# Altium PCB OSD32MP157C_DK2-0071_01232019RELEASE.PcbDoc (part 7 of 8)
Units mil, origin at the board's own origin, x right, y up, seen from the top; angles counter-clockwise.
Board outline 3976.38 x 2795.28 mil, 6 copper layers (Top Layer, Signal Layer 1, Signal Layer 2, Signal Layer 3, Signal Layer 4, Bottom Layer), stack 61.268 mil thick; 404 components, 418 nets, 1720 pads, 1233 vias.
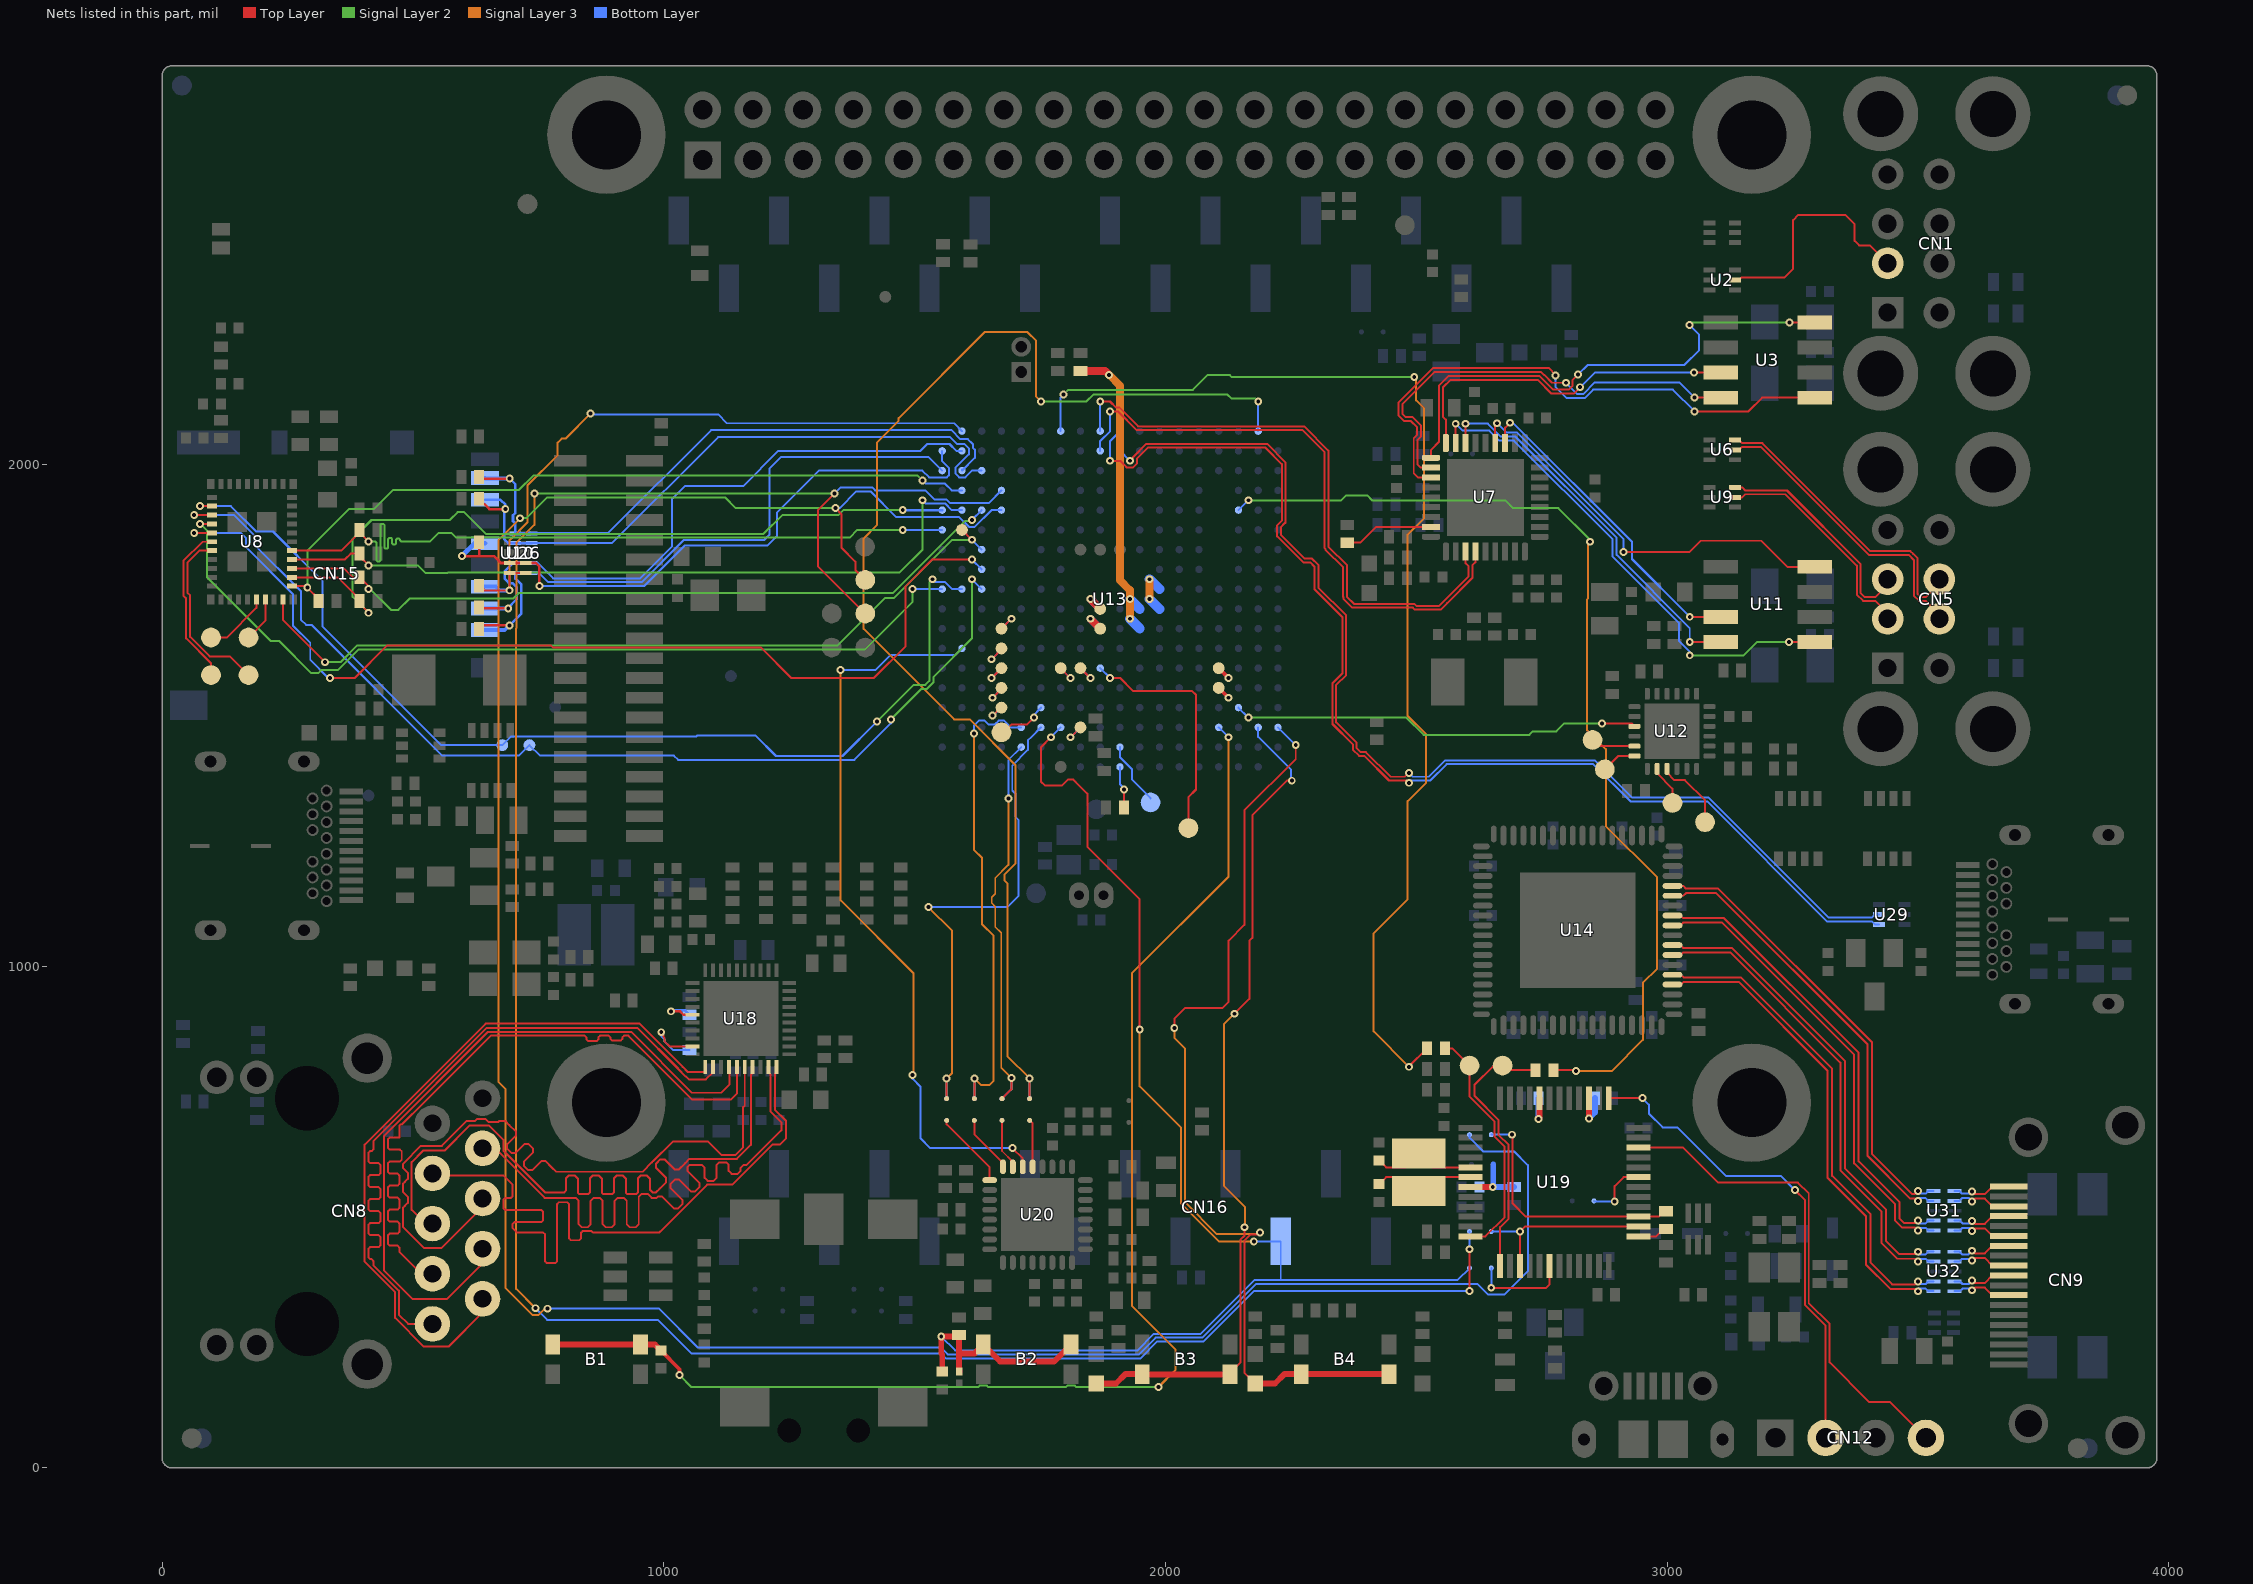
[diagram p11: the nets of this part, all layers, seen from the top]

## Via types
v1: diameter 15.75, hole 7.87, Top Layer to Bottom Layer, tented both sides, 803 vias
v2: diameter 23.62, hole 11.81, Top Layer to Bottom Layer, tented both sides, 417 vias
v3: diameter 15.75, hole 7.87, Top Layer to Bottom Layer, 13 vias

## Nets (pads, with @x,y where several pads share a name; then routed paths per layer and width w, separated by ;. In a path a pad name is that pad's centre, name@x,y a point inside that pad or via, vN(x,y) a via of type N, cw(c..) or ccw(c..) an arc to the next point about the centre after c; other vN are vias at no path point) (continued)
NetR153_2: R153.2 U18.35 | length 86.1
  Top Layer w5.12: v1(1014.76,910.43) 1032.48,910.43 1039.37,903.54 U18.35@1057.09,903.54
  Bottom Layer w5.12: v1(1014.76,910.43) 1020.67,910.43 1022.64,912.4 1042.32,912.4 R153.2@1051.18,903.54
NetR155_1: R155.1 U18.39 | length 158.6
  Top Layer w3.94: v1(995.02,868.7) 995.08,868.65 994.54,868.11 999.02,863.64 999.02,859.56 1001.03,857.54 1001.03,850.98 1011.41,840.6 1025.99,840.6 1026.04,840.55 U18.39@1057.09,840.55
  Bottom Layer w3.94: v1(995.02,868.7) 995.02,860.82 1001.03,854.81 1001.03,850.98 1018.35,833.66 R155.1@1051.18,833.66
NetR159_2: R159.2 U19.44 | length 83.5
  Top Layer w11.81: v1(2744.09,695.87) 2746.06,697.83 U19.44@2746.06,737.2
  Bottom Layer w11.81: v1(2744.09,695.87) R159.2@2744.09,737.2
NetR201_2: R201.2 U13.J1 | length 84
  Top Layer w3.54: R201.2@1917.32,1316.93 v1(1917.32,1352.36)
  Bottom Layer w3.94: U13.J1@1909.45,1397.64 1909.45,1363.43 1917.32,1355.56 v1(1917.32,1352.36)
NetR600_2: R600.2 U7.26 | length 180.1
  Top Layer w3.94: R600.2@2362.45,1844.49 2388.78,1844.49 2420.28,1875.98 U7.26@2529.53,1875.98
NetTP6_1: TP6.1 U8.17 | length 131.7
  Top Layer w3.94: TP6.1@97.45,1655.51 128.95,1655.51 187.99,1714.56 U8.17@187.99,1731.3
NetTP7_1: TP7.1 U8.18 | length 89.6
  Top Layer w3.94: TP7.1@172.25,1655.51 205.71,1688.97 U8.18@205.71,1731.3
NetTP11_1: TP11.1 U8.6 | length 323.3
  Top Layer w3.94: TP11.1@97.44,1580.71 97.44,1604.02 47.76,1653.71 47.76,1733.27 42.3,1738.73 42.3,1808.15 80.61,1846.46 U8.6@99.41,1846.46
NetTP12_1: TP12.1 U8.7 | length 357.5
  Top Layer w3.94: 50.17,1763.58 50.17,1745.11 55.63,1739.65 55.63,1656.97 94.49,1618.11 134.84,1618.11 TP12.1@172.24,1580.71 ; 50.17,1787.6 50.17,1804.88 74.03,1828.74 U8.7@99.41,1828.74 ; 50.2,1763.61 50.2,1787.57
NetTP15_1: TP15.1 U12.11 | length 88.6
  Top Layer w3.94: TP15.1@2851.57,1451.38 2863.98,1438.98 U12.11@2935.04,1438.98
NetTP16_1: TP16.1 U12.12 | length 70.1
  Top Layer w3.94: TP16.1@2875.98,1392.72 2902.56,1419.29 U12.12@2935.04,1419.29
NetTP17_1: TP17.1 U12.14 | length 80.6
  Top Layer w3.94: U12.14@2980.31,1393.7 2980.31,1384.84 3010.83,1354.33 TP17.1@3010.83,1325.79
NetTP18_1: TP18.1 U12.15 | length 149.8
  Top Layer w3.94: U12.15@3000,1393.7 3000,1385.83 3014.76,1371.06 3035.43,1371.06 3075.79,1330.71 TP18.1@3075.79,1287.4
NetTP23_1: TP23.1 U13.K6 | length 484.9
  Top Layer w3.94: v1(1889.76,1574.8) 1909.65,1574.8 1935.24,1549.21 2052.95,1549.21 2061.02,1541.14 2061.02,1352.56 2045.81,1337.35 TP23.1@2045.81,1275.59
  Bottom Layer w3.94: U13.K6@1870.08,1594.49 v1(1889.76,1574.8)
NetTP32_1: TP32.1 U13.N4 | length 103.6
  Top Layer w3.94: TP32.1@1675.2,1468.51 TP32.1@1673.23,1466.54 1677.93,1466.54 1693.68,1482.28 1724.41,1482.28 v1(1738.19,1496.06)
  Bottom Layer w3.94: v1@1735.23,1499.01 U13.N4@1751.97,1515.75
NetTP33_1: TP33.1 U13.J2 | length 127.2
  Bottom Layer w3.94: U13.J2@1909.45,1437.01 1909.45,1416.43 1933.46,1392.41 1933.46,1372.05 TP33.1@1970.47,1335.04
NetTP90_1: TP90.1 U13.K8 | length 55.7
  Top Layer w15.75: v1(1850.39,1692.91) TP90.1@1870.08,1673.23
  Bottom Layer w15.75: v1(1850.39,1692.91) U13.K8@1870.08,1673.23
NetTP91_1: TP91.1 U13.K9 | length 55.7
  Top Layer w15.75: v1(1850.39,1732.28) TP91.1@1870.08,1712.6
  Bottom Layer w15.75: v1(1850.39,1732.28) U13.K9@1870.08,1712.6
NetTP97_1: TP97.1 U13.R6 | length 55.7
  Top Layer w3.94: v3(1653.54,1574.8) TP97.1@1673.23,1594.49
  Bottom Layer w3.94: v3(1653.54,1574.8) U13.R6@1673.23,1594.49
NetTP98_1: TP98.1 U13.R7 | length 59.6
  Top Layer w3.94: v3(1653.54,1612.2) 1673.23,1631.89 TP98.1@1673.23,1633.86
  Bottom Layer w3.94: v3(1653.54,1612.2) 1673.23,1631.89 U13.R7@1673.23,1633.86
NetTP99_1: TP99.1 U13.R8 | length 55.7
  Top Layer w3.94: TP99.1@1673.23,1673.23 v3(1692.91,1692.91)
  Bottom Layer w3.94: U13.R8@1673.23,1673.23 v3(1692.91,1692.91)
NetTP101_1: TP101.1 U13.R5 | length 54
  Top Layer w3.94: v3(1655.51,1535.43) 1673.23,1553.15 TP101.1@1673.23,1555.12
  Bottom Layer w3.94: v3(1655.51,1535.43) 1673.23,1553.15 U13.R5@1673.23,1555.12
NetTP102_1: TP102.1 U13.R4 | length 48.5
  Top Layer w3.94: v3(1655.51,1500) 1671.26,1515.75 TP102.1@1673.23,1515.75
  Bottom Layer w3.94: v3(1655.51,1500) 1656.5,1500 1672.24,1515.75 U13.R4@1673.23,1515.75
NetTP103_1: TP103.1 U13.M6 | length 55.3
  Top Layer w3.54: TP103.1@1791.34,1594.49 1791.34,1594.08 v1(1810.61,1574.8)
  Bottom Layer w3.54: U13.M6@1791.34,1594.49 1791.34,1594.08 v1(1810.61,1574.8)
NetTP104_1: TP104.1 U13.L6 | length 55.7
  Top Layer w3.94: TP104.1@1830.71,1594.49 v1(1850.39,1574.8)
  Bottom Layer w3.94: U13.L6@1830.71,1594.49 v1(1850.39,1574.8)
NOTOC1: U7.13 U11.8 | length 826.3
  Top Layer w3.94: U7.13@2657.48,2043.31 2657.48,2078.74 v1(2661.42,2082.68) ; v1(2913.39,1825.79) 3044.29,1825.79 3066.93,1848.43 3187.99,1848.43 3239.96,1796.46 U11.8@3294.29,1796.46
  Bottom Layer w3.94: v1(2661.42,2082.68) 2680.27,2063.82 2701.19,2063.82 2913.39,1851.63 v1(2913.39,1825.79)
NOTOC2: U7.17 U11.5 | length 1001.4
  Top Layer w3.94: U7.17@2578.74,2043.31 v1(2578.74,2081.69) ; v1(3243.31,1646.46) U11.5@3294.29,1646.46
  Signal Layer 2 w3.94: v1(3045.28,1620.08) 3152.56,1620.08 3178.94,1646.46 v1(3243.31,1646.46)
  Bottom Layer w3.94: v1(2578.74,2081.69) 2578.94,2081.69 2592.72,2067.91 2637.8,2067.91 2637.85,2067.86 2645.61,2067.86 2665.4,2048.07 2694.67,2048.07 2891.73,1851.01 2891.73,1816.82 3023.62,1684.93 3023.62,1648.82 3045.28,1627.17 v1(3045.28,1620.08)
NOTOC3: U3.8 U7.19 | length 1038.1
  Top Layer w3.94: U7.19@2529.53,2013.78 2529.53,2029.53 2545.28,2045.28 2545.28,2157.17 2565.27,2177.17 2745.39,2177.17 2772.95,2149.61 2803.94,2149.61 2812.01,2157.68 2812.01,2169.29 v1(2822.83,2180.12) ; v1(3244.09,2283.46) 3244.29,2283.66 U3.8@3294.29,2283.66
  Signal Layer 2 w3.94: v1(3044.49,2278.78) 3049.18,2283.46 v1(3244.09,2283.46)
  Bottom Layer w3.94: v1(2822.83,2180.12) 2841.54,2198.82 3034.45,2198.82 3063.98,2228.35 3063.98,2259.29 v1(3044.49,2278.78)
NOTOC4: U3.5 U7.21 | length 1139.5
  Top Layer w3.94: U7.21@2529.53,1974.41 2503.94,1974.41 2495.08,1983.27 2495.08,2052.7 2501.96,2059.59 2501.96,2074.26 2488.63,2087.6 2475.2,2087.6 2464.57,2098.23 2464.57,2123.79 2533.69,2192.91 2763.78,2192.91 2778.54,2178.15 v1(2777.56,2178.15) ; v1(3055.12,2106.3) 3162.4,2106.3 3189.76,2133.66 U3.5@3294.29,2133.66
  Bottom Layer w3.94: v1(2777.56,2178.15) 2777.56,2155.51 2800.2,2132.87 2835.94,2132.87 2852.67,2149.61 3011.81,2149.61 v1(3055.12,2106.3)
NRST: B2.1 B2.2 C115.2 CN16.3 R109.1 SB22.2 U13.M3 U35.1 | length 3009.4
  Top Layer w3.94: v1(1771.65,1456.69) 1751.96,1437 1751.96,1368.31 1760.04,1360.23 1793.5,1360.23 1805.32,1372.05 1816.73,1372.05 1820.47,1368.31 1844.49,1344.29 1844.49,1238.19 1948.82,1133.86 v1(1948.82,874.02)
  Top Layer w11.81: C115.2@1555.12,191.93 1555.12,226.38 1553.15,228.35 v1(1553.15,261.81) 1585.63,261.81 R109.1@1588.58,264.76 1588.58,228.35 ; U35.1@1589.57,192.42 1588.58,193.41 1588.58,228.35 ; B2.2@1812.01,246.06 1778.15,212.2 1670.67,212.2 B2.1@1636.81,246.06 1619.09,228.35 1588.58,228.35
  Signal Layer 3 w3.94: v1(1948.82,874.02) 1948.82,760.63 2031.5,677.95 2031.5,526.82 2106.53,451.79 v1(2176.2,451.79)
  Bottom Layer w3.94: v1(1553.15,261.81) 1580.71,234.25 1589.06,234.25 1589.45,233.86 1943.75,233.86 1977.22,267.32 2070.13,267.32 2177.8,375 2582.68,375 SB22.2@2606.3,398.62 ; v1(1771.65,1456.69) U13.M3@1791.34,1476.38 ; v1(2176.2,451.79) CN16.3@2229.92,451.79 2229.92,375.39
OSC_IN: C98.1 U19.5 X5.2 | length 210.6
  Top Layer w3.94: C98.1@2426.18,613.19 2439.96,599.41 2477.36,599.41 X5.2@2504.92,626.97 2532.48,599.41 U19.5@2608.27,599.41
OSC_OUT: C99.1 U19.6 X5.1 | length 210.6
  Top Layer w3.94: C99.1@2426.18,565.94 2439.96,579.72 2477.36,579.72 X5.1@2504.92,552.17 2532.48,579.72 U19.6@2608.27,579.72
PA0_WKUP: TP96.1 U13.L3 | length 55.7
  Top Layer w3.54: v1(1811.02,1456.69) TP96.1@1830.71,1476.38
  Bottom Layer w3.94: v1(1811.02,1456.69) U13.L3@1830.71,1476.38
PA13: B4.1 B4.2 LD6.2 U13.A3 | length 1896.2
  Top Layer w3.94: v1(2017.72,876.97) 2017.72,895.67 2039.37,917.32 2114.17,917.32 2125.98,929.13 2125.98,1051.18 2157.48,1082.68 2157.48,1310.83 2259.84,1413.19 v1(2259.84,1440.94) ; LD6.2@2179.13,168.31 2157.48,189.96 2157.48,452.56 2170.49,465.57 2184.67,465.57 v1(2188.19,469.09)
  Top Layer w11.81: LD6.2@2179.13,168.31 2218.5,168.31 2237.2,187.01 B4.2@2270.67,187.01 B4.1@2445.87,187.01
  Signal Layer 3 w3.94: v1(2017.72,876.97) 2017.72,857.68 2039.37,836.02 2039.37,529.53 2102.76,466.14 2185.24,466.14 v1(2188.19,469.09)
  Bottom Layer w3.94: U13.A3@2224.41,1476.38 v1(2259.84,1440.94)
PA14: B3.1 B3.2 LD5.2 U13.B3 | length 1694.6
  Top Layer w3.94: B3.1@2128.94,187.01 2128.94,189.57 2149.61,210.24 2149.61,455.26 2157.68,463.33 v1(2157.68,479.92) ; v1@2137.68,907.46 v1(2137.68,905.51) 2167.32,935.15 2167.32,1050.98 2173.23,1056.89 2173.23,1301.18 2242.12,1370.08 v1(2251.96,1370.08)
  Top Layer w11.81: LD5.2@1862.2,168.31 1901.57,168.31 1920.28,187.01 B3.2@1953.74,187.01 1954.72,186.02 2123.43,186.02 2128.94,180.51 B3.1@2128.94,187.01
  Signal Layer 3 w3.94: v1(2137.68,905.51) 2116.34,884.17 2116.34,562.8 2158.46,520.67 v1@2158.46,479.33
  Bottom Layer w3.94: U13.B3@2185.04,1476.38 2185.04,1457.59 2250,1392.63 2250,1372.04 v1(2251.96,1370.08)
PMIC_WAKEUP: TP53.1 U13.D6 | length 55.7
  Top Layer w7.87: TP53.1@2106.3,1594.49 v1(2125.98,1574.8)
  Bottom Layer w3.94: U13.D6@2106.3,1594.49 v1(2125.98,1574.8)
PONKEY_n: B1.3 B1.4 C114.2 U13.D3 | length 2708.7
  Top Layer w7.87: C114.2@994.09,234.25 1031.5,196.85 v1(1031.5,185.04)
  Top Layer w11.81: B1.4@777.56,245.08 B1.4@778.54,246.06 B1.3@953.74,246.06 982.28,246.06 C114.2@994.09,234.25
  Signal Layer 2 w3.94: v1(1031.5,185.04) 1055.12,161.42 1626.52,161.42 1629.47,164.37 1644.15,164.37 1647.1,161.42 1801.72,161.42 1804.67,164.37 1819.35,164.37 1822.3,161.42 v1(1986.22,161.42)
  Signal Layer 3 w3.94: v1(1986.22,161.42) 2019.68,194.88 2019.68,236.67 1933.07,323.28 1933.07,986.22 2125.98,1179.13 v1(2125.98,1456.69)
  Bottom Layer w3.94: U13.D3@2106.3,1476.38 v1(2125.98,1456.69)
PRTPWR1: U7.12 U11.3 | length 645
  Top Layer w3.94: U7.12@2677.17,2043.31 2677.17,2073.82 v1(2687.01,2083.66) ; v1(3045.28,1696.85) 3045.67,1696.46 U11.3@3107.28,1696.46
  Bottom Layer w3.94: v1(2687.01,2083.66) 2692.49,2083.66 2930.12,1846.03 2930.12,1812.01 v1(3045.28,1696.85)
PRTPWR2: U7.16 U11.4 | length 763.8
  Top Layer w3.94: U7.16@2598.43,2043.31 v1(2598.43,2081.69) ; v1(3045.28,1646.65) 3107.09,1646.65 U11.4@3107.28,1646.46
  Bottom Layer w3.94: v1(2598.43,2081.69) 2642.91,2081.69 2668.66,2055.95 2697.93,2055.95 2899.61,1854.27 2899.61,1820.08 3045.28,1674.41 v1(3045.28,1646.65)
PRTPWR3: U3.3 U7.18 | length 702.3
  Top Layer w3.94: U7.18@2559.06,2043.31 2559.06,2089.67 2553.15,2095.57 2553.15,2153.91 2568.53,2169.29 2742.13,2169.29 2769.68,2141.73 2813.98,2141.73 v1(2826.77,2154.53) ; v1(3054.13,2183.66) U3.3@3107.28,2183.66
  Bottom Layer w3.94: v1(2826.77,2154.53) 2855.91,2183.66 v1(3054.13,2183.66)
PRTPWR4: U3.4 U7.20 | length 878.2
  Top Layer w3.94: U7.20@2529.53,1994.09 2508.86,1994.09 2502.95,2000 2502.95,2049.44 2509.84,2056.33 2509.84,2077.52 2491.89,2095.47 2478.46,2095.47 2472.44,2101.49 2472.44,2120.53 2536.95,2185.04 2748.65,2185.04 2754.55,2179.13 2754.92,2179.13 2770.67,2163.39 v1(2798.23,2163.39) ; v1(3055.12,2133.66) U3.4@3107.28,2133.66
  Bottom Layer w3.94: v1(2798.23,2163.39) 2820.87,2140.75 2832.68,2140.75 2856.3,2164.37 3024.41,2164.37 v1(3055.12,2133.66)
PWR_EXT: R158.1 U19.39 | length 85.6
  Top Layer w11.81: v1(2844.49,696.85) U19.39@2844.49,737.2
  Bottom Layer w11.81: v1(2844.49,696.85) 2856.3,708.66 R158.1@2856.3,737.2
PWR_ON: TP93.1 U13.D5 | length 55.7
  Top Layer w7.87: TP93.1@2106.3,1555.12 v1(2125.98,1535.43)
  Bottom Layer w3.94: U13.D5@2106.3,1555.12 v1(2125.98,1535.43)
RJ45_D1_N: CN8.10 U18.2 | length 1441.6
  Top Layer w3.94: CN8.10@538.78,287.2 490.35,287.2 472.05,305.51 472.05,353.49 421.26,404.28 421.26,412.66 417.67,416.25 414.61,416.25 411.02,419.84 411.02,436.59 414.61,440.19 421.26,440.19 431.5,440.19 435.09,443.78 435.09,460.53 431.5,464.12 421.26,464.12 414.61,464.12 411.02,467.71 411.02,484.47 414.61,488.06 421.26,488.06 431.5,488.06 435.09,491.65 435.09,508.41 431.5,512 421.26,512 414.61,512 411.02,515.59 411.02,532.34 414.61,535.93 421.26,535.93 431.5,535.93 435.09,539.52 435.09,556.28 431.5,559.87 421.26,559.87 414.61,559.87 411.02,563.46 411.02,580.22 414.61,583.81 421.26,583.81 431.5,583.81 435.09,587.4 435.09,604.15 431.5,607.74 421.26,607.74 414.61,607.74 411.02,611.33 411.02,628.09 414.61,631.68 417.67,631.68 421.26,635.27 421.26,651.53 422.27,652.54 646.5,876.77 948.03,876.77 1028.4,796.41 1028.4,796.04 1044.08,780.35 1044.45,780.35 1050.2,774.61 1084.14,774.61 1098.43,788.89 U18.2@1098.43,799.21
RJ45_D1_P: CN8.9 U18.1 | length 1452.7
  Top Layer w3.94: CN8.9@638.78,337.2 638.78,310.04 570.87,242.13 521.65,242.13 464.57,299.21 464.57,350.39 403.54,411.42 403.54,644.39 644.98,885.83 951.78,885.83 1037.45,800.16 1037.45,799.79 1047.83,789.41 1082.68,789.41 U18.1@1082.68,799.21
RJ45_D2_N: CN8.8 U18.5 | length 1399.9
  Top Layer w3.94: CN8.8@523.23,387.2 516.73,387.2 472.83,431.1 472.83,439.48 469.24,443.07 453.64,443.07 450.05,446.66 450.05,463.42 453.64,467.01 469.24,467.01 472.83,470.6 472.83,487.35 469.24,490.94 453.64,490.94 450.05,494.54 450.05,511.29 453.64,514.88 469.24,514.88 472.83,518.47 472.83,535.23 469.24,538.82 453.64,538.82 450.05,542.41 450.05,559.17 453.64,562.76 469.24,562.76 472.83,566.35 472.83,583.1 469.24,586.69 453.64,586.69 450.05,590.28 450.05,607.04 453.64,610.63 472.83,610.63 474.07,610.63 477.66,614.22 477.66,630.98 474.07,634.57 472.83,634.57 453.64,634.57 450.05,638.16 450.05,654.91 453.64,658.5 472.09,658.5 472.83,659.25 472.83,681.95 475.91,685.03 478.14,685.03 521.66,728.54 521.85,728.54 655.12,861.81 755.91,861.81 773.94,861.81 797.87,861.81 821.81,861.81 842.16,861.81 845.75,858.22 845.75,854.37 849.34,850.78 866.09,850.78 869.68,854.37 869.68,858.22 873.28,861.81 890.03,861.81 893.62,858.22 893.62,855.43 897.21,851.84 913.97,851.84 917.56,855.43 917.56,858.22 921.15,861.81 929.53,861.81 1057.09,734.25 1133.86,734.25 1145.67,746.06 U18.5@1145.67,799.21
RJ45_D2_P: CN8.7 U18.4 | length 1413.2
  Top Layer w3.94: CN8.7@638.78,437.2 638.78,408.46 566.93,336.61 499.5,336.61 442.57,393.55 442.57,662.26 649.6,869.29 934.85,869.29 1056.11,748.03 1114.57,748.03 1130.71,764.17 1130.71,786.61 1129.92,787.4 U18.4@1129.92,799.21
RJ45_D3_N: CN8.6 U18.7 | length 1430
  Top Layer w3.94: CN8.6@538.78,487.2 524.61,487.2 497.24,514.57 497.24,609.7 520.03,632.48 520.29,632.48 520.68,632.87 562.99,632.87 612.6,682.48 651.97,682.48 680.12,654.33 680.12,632.87 763.78,549.21 801.18,549.21 804.72,552.76 804.72,577.09 810.71,583.07 822.68,583.07 828.66,577.09 828.66,549.21 831.81,546.06 849.45,546.06 852.6,549.21 852.6,577.09 858.58,583.07 870.55,583.07 876.54,577.09 876.54,549.21 879.69,546.06 897.32,546.06 900.47,549.21 900.47,577.09 906.46,583.07 918.43,583.07 924.41,577.09 924.41,549.21 927.56,546.06 945.2,546.06 948.35,549.21 948.35,577.09 954.33,583.07 966.3,583.07 972.28,577.09 972.28,555.2 978.27,549.21 984.25,549.21 991.94,556.9 1004.63,569.6 1004.63,578.06 984.55,598.14 984.55,606.6 993.02,615.07 1001.48,615.07 1021.56,594.98 1030.02,594.98 1042.72,607.68 1051.18,616.14 1145.67,616.14 1173.82,644.29 1173.82,784.06 1177.17,787.4 U18.7@1177.17,799.21
RJ45_D3_P: CN8.5 U18.6 | length 1451.5
  Top Layer w3.94: CN8.5@638.78,537.2 638.78,520.67 557.09,438.98 521.65,438.98 480.31,480.31 480.31,498.58 480.31,519.05 483.78,522.52 489.77,528.5 489.77,540.47 483.78,546.46 480.31,549.92 480.31,566.93 483.78,570.39 489.77,576.38 489.77,588.35 483.78,594.33 480.31,597.8 480.31,606.3 515.94,641.93 557.53,641.93 607.53,691.93 624.21,691.93 628.15,695.87 644.21,695.87 648.15,691.93 650.12,689.96 670.12,689.96 672.09,691.93 684.06,691.93 692.34,683.64 705.03,670.95 705.03,662.49 687.6,645.05 687.6,636.59 696.06,628.12 704.52,628.12 721.96,645.56 730.42,645.56 738.89,637.1 738.89,628.63 721.14,610.89 721.14,602.43 729.6,593.96 738.07,593.96 755.81,611.71 764.28,611.71 776.97,599.01 785.43,590.55 957.93,590.55 976.43,609.06 979.53,612.15 1015.01,647.64 1018.56,651.18 1087.74,651.18 1115.3,623.62 1142.57,623.62 1158.27,639.32 1158.27,719.29 1161.42,722.44 U18.6@1161.42,799.21
RJ45_D4_N: CN8.4 U18.10 | length 1441.6
  Top Layer w3.94: CN8.4@538.78,587.2 542.52,583.46 680.31,583.46 698.82,564.96 698.82,549.21 698.82,541.78 695.23,538.19 683.62,538.19 680.03,534.6 680.03,517.84 683.62,514.25 698.82,514.25 755.86,514.25 759.45,510.66 759.45,493.91 755.86,490.31 702.41,490.31 698.82,486.72 698.82,478.35 708.07,469.09 715.47,469.09 739.41,469.09 759.76,469.09 763.35,465.5 763.35,412.06 766.94,408.46 783.69,408.46 787.28,412.06 787.28,469.09 787.28,526.13 790.87,529.72 807.63,529.72 811.22,526.13 811.22,469.09 811.22,457.6 814.81,454.01 831.57,454.01 835.16,457.6 835.16,469.09 838.5,472.44 855.75,472.44 859.09,469.09 883.03,469.09 906.97,469.09 930.91,469.09 954.84,469.09 978.78,469.09 990.75,469.09 992.72,471.06 1086.61,564.96 1136.56,564.96 1216.29,644.69 1231.3,644.69 1243.31,656.69 1243.31,692.73 1221.46,714.58 1221.46,785.43 1224.41,788.39 U18.10@1224.41,799.21
RJ45_D4_P: CN8.3 U18.9 | length 1421
  Top Layer w3.94: U18.9@1208.66,799.21 1208.66,788.39 1212.4,784.65 1212.4,710.83 1234.25,688.98 1234.25,673.23 1165.35,604.33 1159.37,604.33 1153.39,598.35 1153.39,592.36 1147.4,586.38 1135.43,586.38 1129.45,592.36 1129.45,604.33 1125.12,608.66 1109.84,608.66 1105.51,604.33 1105.51,578.42 1099.53,572.44 1087.56,572.44 1081.57,578.42 1081.57,598.35 1075.59,604.33 1057.64,604.33 1051.77,604.33 1047.54,600.1 1047.54,591.64 1070.9,568.28 1070.9,559.82 1062.43,551.35 1053.97,551.35 1030.61,574.71 1022.15,574.71 1013.69,566.25 1013.69,557.78 1037.04,534.43 1037.04,525.97 1028.58,517.5 1020.12,517.5 996.76,540.86 988.3,540.86 986.02,538.58 975.88,538.58 974.06,540.41 968.07,546.39 956.1,546.39 950.12,540.41 950.12,538.58 950.12,485.9 944.13,479.92 932.17,479.92 926.18,485.9 926.18,532.6 920.2,538.58 908.23,538.58 902.24,532.6 902.24,485.9 896.26,479.92 884.29,479.92 878.31,485.9 878.31,532.6 872.32,538.58 860.35,538.58 854.37,532.6 854.37,485.9 848.39,479.92 836.42,479.92 830.43,485.9 830.43,532.6 824.45,538.58 806.5,538.58 801.18,538.58 762.6,538.58 663.98,637.2 CN8.3@638.78,637.2 CN8.3@618.7,637.2 ; CN8.3@618.7,637.2 611.61,637.2 615.16,640.75 CN8.3@618.7,637.2
SAI2_FSA: SB1.1 U20.1 | length 154.6
  Top Layer w3.94: SB1.1@1563.98,692.91 1563.98,685.04 1649.61,599.41 U20.1@1649.61,573.82
SAI2_FSAM: SB1.2 SB16.2 U13.N3 | length 1000.4
  Top Layer w3.94: SB1.2@1563.98,736.22 v1(1563.98,776.57)
  Signal Layer 3 w3.94: v1(1527.56,1118.11) 1574.8,1070.87 1574.8,787.4 v1(1563.98,776.57)
  Bottom Layer w3.94: v1(1527.56,1118.11) 1685.04,1118.11 1707.56,1140.63 1707.56,1291.49 1700.79,1298.26 1700.79,1344.49 1694.68,1350.59 1694.68,1400.3 1725.89,1431.5 1725.89,1450.3 1732.28,1456.69 U13.N3@1751.97,1476.38 ; SB16.2@1563.98,736.22 v1(1563.98,776.57)
SAI2_MCLKA: U13.U7 U20.30 | length 1501.3
  Top Layer w3.94: v1(1694.88,637.8) 1715.55,617.13 U20.30@1715.55,600.39
  Signal Layer 3 w3.94: v1(1352.36,1590.55) 1352.36,1131.52 1497.8,986.08 1497.8,785.21 v1(1496.06,783.46)
  Bottom Layer w3.94: v1(1352.36,1590.55) 1421.26,1590.55 1451.28,1620.57 1581.2,1620.57 U13.U7@1594.49,1633.86 ; v1(1496.06,783.46) 1496.06,775.59 1511.81,759.84 1511.81,657.28 1531.3,637.8 v1(1694.88,637.8) v1@1697.26,640.18
SAI2_SCKA: SB3.1 U20.31 | length 101.5
  Top Layer w3.54: SB3.1@1674.21,692.91 1674.21,631.89 1695.87,610.24 U20.31@1695.87,600.39
SAI2_SCKAM: SB3.2 SB14.2 U13.P2 | length 798.2
  Top Layer w3.94: SB3.2@1674.21,736.22 1692.91,754.92 v1(1692.91,777.56)
  Signal Layer 3 w3.54: v1(1687.01,1334.65) 1687.01,1202.27 1660.83,1176.09 1660.83,1144.6 1653.74,1137.52 1653.74,1126.26 1660.83,1119.18 1660.83,1078.49 1672.63,1066.69 1672.63,797.84 v1(1692.91,777.56)
  Bottom Layer w3.54: v1(1687.01,1334.65) 1687.01,1411.42 U13.P2@1712.6,1437.01
  Bottom Layer w3.94: SB14.2@1674.21,736.22 1692.91,754.92 v1(1692.91,777.56)
SAI2_SDA: SB2.1 U20.32 | length 116.2
  Top Layer w3.94: SB2.1@1619.09,692.91 1619.09,665.35 1676.18,608.27 U20.32@1676.18,600.39
SAI2_SDAM: SB2.2 SB15.2 U13.P3 | length 963.1
  Top Layer w3.94: SB2.2@1619.09,736.22 v1(1619.09,776.57)
  Signal Layer 3 w3.94: v1(1618.11,1464.56) 1618.11,1304.92 1618.11,1293.51 1618.11,1232.29 1634.35,1216.04 1634.35,1084.09 1657.48,1060.97 1657.48,771.85 1649.41,763.78 1631.89,763.78 v1(1619.09,776.57) v1@1618.31,777.36
  Bottom Layer w3.94: v1(1618.11,1464.56) 1618.11,1479.42 1628.35,1489.67 1639.76,1489.67 1647.15,1482.28 1660.34,1482.28 1667.72,1489.67 1678.73,1489.67 1692.02,1476.38 U13.P3@1712.6,1476.38 ; SB15.2@1619.09,736.22 v1(1619.09,776.57)
SAI2_SDB: SB4.1 U20.29 | length 95
  Top Layer w3.94: SB4.1@1729.33,692.91 1735.24,687.01 U20.29@1735.24,600.39
SAI2_SDBM: SB4.2 SB13.2 U13.B18 | length 2580.2
  Top Layer w3.94: SB4.2@1729.33,736.22 v1(1729.33,776.57)
  Signal Layer 2 w3.94: v1(1751.97,2125.98) 1842.52,2125.98 1856.3,2139.76 2123.82,2139.76 2131.89,2131.69 2179.33,2131.69 v1(2185.04,2125.98)
  Signal Layer 3 w3.94: v1(1729.33,776.57) 1685.04,820.87 1685.04,1165.55 1679.13,1171.46 1679.13,1182.87 1700.79,1204.53 1700.79,1401.37 1609.76,1492.4 1578.66,1492.4 1398.43,1672.64 1398.43,1852.95 1424.8,1879.33 1424.8,2044.15 1468.11,2087.45 1468.11,2092.66 1640.02,2264.57 1724.83,2264.57 1742.13,2247.27 1742.13,2135.83 v1(1751.97,2125.98)
  Bottom Layer w3.94: SB13.2@1729.33,736.22 v1(1729.33,776.57) ; U13.B18@2185.04,2066.93 v1(2185.04,2125.98)
SDMMC1_CK: CN15.5 R19.1 U10.2 U10.9 U13.V17 | length 1288.2
  Top Layer w5.12: v1(597.44,1817.91) 630.91,1817.91 ; R19.1@631.89,1845.47 631.89,1818.9 630.91,1817.91 ; v1(751.97,1757.87) 751.97,1797.24 745.08,1804.13 U10.2@724.8,1804.13 U10.9@692.52,1804.13 675.2,1804.13 661.42,1817.91 630.91,1817.91
  Bottom Layer w3.94: v1(751.97,1757.87) 960.63,1757.87 1041.34,1838.58 1206.69,1838.58 1225.39,1857.28 1225.39,1904.53 1309.06,1988.19 1515.55,1988.19 1528.84,1974.9 1564.47,1974.9 1568.41,1978.84 1568.41,1993.69 1555.12,2006.98 U13.V17@1555.12,2027.56
  Bottom Layer w9.84: v1(597.44,1817.91) 623.03,1843.5 CN15.5@643.7,1843.5
SDMMC1_CMD: CN15.3 R25.1 U10.1 U10.10 U13.U18 | length 1367
  Top Layer w3.94: R25.1@638.78,1751.97 636.47,1749.66 v1(692.52,1749.66) U10.10@692.52,1784.45 U10.1@724.8,1784.45
  Top Layer w7.87: R25.1@631.89,1758.86 R25.1@638.78,1751.97
  Signal Layer 3 w3.94: v1(692.52,1749.66) 692.52,1849.48 728.35,1885.3 728.35,1958.66 788.39,2018.7 788.39,2044.09 796.46,2052.17 804.13,2052.17 v1(854.33,2102.36)
  Bottom Layer w3.94: v1(854.33,2102.36) 856.3,2100.39 1108.27,2100.39 1125.98,2082.68 1578.74,2082.68 U13.U18@1594.49,2066.93
  Bottom Layer w7.87: CN15.3@643.7,1756.89 665.65,1756.89 672.89,1749.66 v1(692.52,1749.66)
SDMMC1_D0: CN15.7 R16.1 U13.T16 U26.4 U26.7 | length 1323
  Top Layer w5.12: R16.1@631.89,1932.09 652.47,1911.51 v1(684.09,1911.51)
  Bottom Layer w3.94: U26.7@736.61,1843.5 896.65,1843.5 1108.26,2055.11 1570.87,2055.11 1585.14,2040.85 1599.99,2040.85 1608.27,2032.57 1608.27,2020.76 1581.2,1993.69 1581.2,1982.69 1588.98,1974.9 1601.08,1974.9 1614.37,1988.19 U13.T16@1633.86,1988.19
  Bottom Layer w5.12: CN15.7@643.7,1930.12 674.21,1930.12 684.09,1920.24 v1(684.09,1911.51) ; v1@682.09,1911.51 682.09,1851.38 689.96,1843.5 U26.4@704.33,1843.5 U26.7@736.61,1843.5
SDMMC1_D1: CN15.8 R14.1 U13.U16 U26.5 U26.6 | length 1305.7
  Top Layer w5.12: R14.1@631.89,1975.39 634.84,1972.44 v1(692.91,1972.44)
  Bottom Layer w3.94: 888.78,1863.19 1094.49,2068.9 1573.73,2068.9 1591.45,2051.18 1606.3,2051.18 1616.14,2041.34 1616.14,2034.14 1620.08,2030.2 1620.08,2013.78 U13.U16@1594.49,1988.19 U13.U16@1594.49,1990.16
  Bottom Layer w5.12: v1(692.91,1972.44) 704.33,1961.02 704.33,1904.18 699.41,1899.26 699.41,1887.35 704.33,1882.43 U26.5@704.33,1863.19 U26.6@736.61,1863.19 888.78,1863.19
  Bottom Layer w7.87: CN15.8@643.7,1973.43 644.69,1972.44 v1(692.91,1972.44)
SDMMC1_D2: CN15.1 R33.1 U13.V16 U26.1 U26.10 | length 1286.5
  Top Layer w5.12: R33.1@631.89,1672.24 639.42,1679.77 v1(692.52,1679.77)
  Bottom Layer w3.94: U26.1@704.33,1784.45 U26.10@736.61,1784.45 750.98,1784.45 769.69,1765.75 955.71,1765.75 1040.35,1850.39 1200.79,1850.39 1210.63,1860.24 1210.63,1992.13 1234.25,2015.75 1527.56,2015.75 U13.V16@1555.12,1988.19
  Bottom Layer w5.12: v1(692.52,1679.77) 715.94,1703.2 715.94,1761.42 704.33,1773.03 U26.1@704.33,1784.45
  Bottom Layer w7.87: CN15.1@643.7,1670.28 683.02,1670.28 v1(692.52,1679.77)
SDMMC1_D3: CN15.2 R28.1 U13.U17 U26.2 U26.9 | length 1302.2
  Top Layer w5.12: R28.1@631.89,1715.55 633.86,1713.58 v1(689.96,1713.58)
  Bottom Layer w3.94: U26.2@704.33,1804.13 U26.9@736.61,1804.13 749.02,1804.13 779.53,1773.62 952.76,1773.62 1016.73,1837.6 1016.73,1932.09 1041.87,1957.23 1158.02,1957.23 1228.35,2027.56 1511.81,2027.56 1525.59,2041.34 1569.57,2041.34 1583.35,2027.56 U13.U17@1594.49,2027.56
  Bottom Layer w5.12: v1@688.44,1713.58 706.89,1732.03 706.89,1755.61 698.47,1764.03 691.45,1764.03 683.07,1772.41 683.07,1787.73 699.47,1804.13 U26.2@704.33,1804.13
  Bottom Layer w7.87: CN15.2@643.7,1713.58 v1@688.44,1713.58
SDMMC2_CK: TP25.1 U8.20 U13.T12 | length 1605.8
  Top Layer w3.94: U8.20@241.14,1731.3 241.14,1689.97 v1(324.8,1606.31) ; TP25.1@1594.49,1870.08 v1(1614.17,1850.39)
  Signal Layer 2 w3.94: v1(324.8,1606.31) 355.57,1606.31 389.03,1639.76 1346.46,1639.76 1440.94,1734.25 1458.66,1734.25 1574.8,1850.39 v1(1614.17,1850.39)
  Bottom Layer w3.94: v1(1614.17,1850.39) U13.T12@1633.86,1830.71
SDMMC2_CMD: R26.2 U8.22 U13.U15 | length 1520.8
  Top Layer w3.94: U8.22@258.86,1757.87 286.43,1757.87 v1(289.37,1754.93) 312.02,1732.28 R26.2@312.02,1728.35
  Signal Layer 2 w3.94: v1(289.37,1754.93) 289.37,1828.74 372.05,1911.42 422.24,1911.42 460.63,1949.8 711.42,1949.8 739.96,1978.35 1505.91,1978.35 v1(1515.75,1968.5)
  Bottom Layer w3.94: v1(1515.75,1968.5) 1522.15,1962.11 1560.62,1962.11 1573.91,1948.82 U13.U15@1594.49,1948.82
SDMMC2_D0: R22.2 U8.24 U13.T14 | length 1495
  Top Layer w3.94: U8.24@258.86,1793.31 362.01,1793.31 379.72,1775.59 R22.2@393.71,1775.59 411.45,1757.85 v1(411.45,1752.05)
  Signal Layer 2 w3.94: v1(411.45,1752.05) 414.83,1752.05 456.25,1710.63 470.93,1710.63 493.57,1733.27 699.8,1733.27 710.63,1744.09 1456.69,1744.09 1600.59,1887.99 1612.4,1887.99 v1(1614.17,1889.76)
  Bottom Layer w3.94: v1(1614.17,1889.76) U13.T14@1633.86,1909.45
SDMMC2_D1: R17.2 U8.26 U13.V13 | length 1541.9
  Top Layer w3.94: U8.26@258.86,1828.74 357.29,1828.74 R17.2@393.71,1865.16 ; R17.2@393.71,1870.08 R17.2@393.71,1865.16 ; v1(411.45,1846.54) 393.71,1864.28 R17.2@393.71,1865.16
  Signal Layer 2 w3.94: v1(411.45,1846.54) 425.2,1846.54 427.08,1844.65 427.08,1809.14 429.44,1806.77 432.59,1806.77 434.96,1809.14 434.96,1846.54 434.96,1879.92 437.32,1882.28 440.47,1882.28 442.83,1879.92 442.83,1846.54 442.83,1834.99 445.19,1832.63 448.34,1832.63 450.7,1834.99 450.7,1846.54 450.7,1851.61 453.07,1853.97 456.22,1853.97 458.58,1851.61 458.58,1846.54 458.58,1842.91 460.94,1840.55 464.09,1840.55 466.45,1842.91 466.45,1846.54 466.45,1850.79 468.81,1853.15 471.96,1853.15 474.33,1850.79 474.33,1848.9 476.69,1846.54 482.2,1846.54 490.07,1846.54 497.95,1846.54 505.82,1846.54 513.7,1846.54 521.57,1846.54 529.44,1846.54 533.38,1846.54 551.02,1864.17 576.77,1864.17 586.22,1854.72 1370.47,1854.72 1385.83,1870.08 v1(1476.38,1870.08)
  Bottom Layer w3.94: v1(1476.38,1870.08) U13.V13@1555.12,1870.08
SDMMC2_D2: R27.2 U8.23 U13.V14 | length 1585.8
  Top Layer w3.94: U8.23@258.86,1775.59 350.21,1775.59 393.71,1732.09 R27.2@393.71,1728.35 393.71,1722.55 v1(411.45,1704.81) v1@411.45,1704.75
  Signal Layer 2 w3.94: v1@413.5,1702.76 v1(411.45,1704.81) 379.92,1736.34 379.92,1852.36 417.32,1889.76 573.37,1889.76 589.12,1905.51 601.83,1905.51 645.13,1862.2 1198.82,1862.2 1236.22,1899.61 1348.23,1899.61 1358.07,1909.45 v1(1476.38,1909.45)
  Bottom Layer w5.12: v1(1476.38,1909.45) U13.V14@1555.12,1909.45
SDMMC2_D3: R20.2 U8.25 U13.U14 | length 1485.4
  Top Layer w3.94: U8.25@258.86,1811.02 363.78,1811.02 375.59,1822.83 R20.2@393.71,1822.83 393.71,1817.04 v1(411.45,1799.3)
  Signal Layer 2 w3.94: v1(411.45,1799.3) 509.76,1799.3 524.61,1784.45 569.35,1784.45 570.33,1785.43 1470.27,1785.43 1515.75,1830.91 v1(1515.75,1929.13)
  Bottom Layer w3.94: v1(1515.75,1929.13) 1522.15,1922.74 1560.62,1922.74 1573.91,1909.45 U13.U14@1594.49,1909.45
STLINK_RX: R72.2 TP21.1 U19.13 | length 538.1
  Top Layer w3.94: U19.13@2667.32,402.56 2667.32,480.01 2684.06,496.74 2684.06,644.01 2664.37,663.69 2664.37,693.53 2616.14,741.76 2616.14,763.78 2654.53,802.17 TP21.1@2672.24,802.17 2681.5,792.91 R72.2@2738.19,792.91
STLINK_SWCLK: SB20.2 TP5.1 U13.R15 | length 4986.1
  Top Layer w3.94: v1(1340.55,1942.91) 1307.09,1909.45 1307.09,1798.03 TP5.1@1401.77,1703.35 ; v1(2606.3,436.02) 2606.3,353.15 v1(2606.54,352.92)
  Signal Layer 2 w3.94: v1(742.13,1942.91) v1(1340.55,1942.91)
  Signal Layer 3 w3.94: v1(742.13,1942.91) 742.13,1879.92 706.3,1844.09 706.3,1674.06 705.71,1673.47 705.71,357.09 v1(744.29,318.5)
  Bottom Layer w3.94: v1(744.29,318.5) 767.52,295.28 988.19,295.28 1055.12,228.35 1552.59,228.35 1562.43,218.5 1582.54,218.5 1582.93,218.11 1949.72,218.11 1983.97,252.36 2076.32,252.36 2176.88,352.92 v1(2606.54,352.92) ; v1(1340.55,1942.91) 1352.36,1954.72 1415.35,1954.72 1421.26,1948.82 1521.65,1948.82 1539.37,1931.1 1563.39,1931.1 1571.27,1923.23 1647.64,1923.23 U13.R15@1673.23,1948.82 ; v1(2606.3,436.02) SB20.2@2606.3,471.46
STLINK_SWDIO: SB17.2 TP3.1 U13.R14 | length 5315.6
  Top Layer w3.94: v1(1342.52,1913.39) 1354.33,1901.57 1354.33,1834.44 1381.89,1806.89 1381.89,1790.16 TP3.1@1401.77,1770.28
  Signal Layer 2 w3.94: v1(713.78,1893.31) 725.98,1893.31 767.72,1935.04 1122.05,1935.04 1143.7,1913.39 v1(1342.52,1913.39)
  Signal Layer 3 w3.94: v1(713.78,1893.31) 670.28,1849.8 670.28,769.74 684.06,755.96 684.06,359.25 738.58,304.72 750,304.72 762.79,317.52 v1(767.91,317.52)
  Bottom Layer w3.94: v1(767.91,317.52) 990.72,317.52 1068.08,240.16 1551.91,240.16 1565.69,226.38 1585.8,226.38 1586.19,225.98 1946.46,225.98 1980.31,259.84 2073.22,259.84 2180.08,366.7 2622.67,366.7 2643.9,345.47 2675.79,345.47 2722.64,392.32 2722.64,603.94 2695.67,630.91 2633.66,630.91 2606.3,658.27 SB17.2@2606.3,664.37 ; v1(1342.52,1913.39) 1350.39,1913.39 1383.86,1946.85 1412.09,1946.85 1463.27,1895.67 1588.78,1895.67 1608.47,1875.98 1619.88,1875.98 1653.35,1909.45 U13.R14@1673.23,1909.45
STLINK_TX: R77.1 TP20.1 U19.12 | length 478.4
  Top Layer w3.94: R77.1@2557.09,836.61 2571.85,836.61 TP20.1@2606.3,802.17 2606.3,740.47 2656.5,690.27 2656.5,660.43 2676.18,640.75 2676.18,500 2637.8,461.61 U19.12@2608.27,461.61
STM_JTCK: CN12.2 U19.37 | length 976.7
  Top Layer w3.94: U19.37@2883.86,737.2 v1(2950.79,737.2) ; v1(3254.92,554.13) 3274.61,534.45 3274.61,325.48 3316.14,283.94 CN12.2@3316.14,60.04
  Bottom Layer w3.94: v1(2950.79,737.2) 2963.58,724.41 2963.58,706.69 2991.14,679.13 3020.67,679.13 3118.11,581.69 3227.36,581.69 v1(3254.92,554.13)
STM_JTMS: CN12.4 U19.34 | length 985.9
  Top Layer w3.94: U19.34@2942.91,638.78 3032.17,638.78 3102.05,568.9 3260.83,568.9 3282.48,547.24 3282.48,328.74 3324.02,287.2 3324.02,210.43 3402.56,131.89 3444.29,131.89 CN12.4@3516.14,60.04
STM_RST: C182.2 R161.1 SB18.2 U19.7 | length 157.9
  Top Layer w11.81: U19.7@2608.27,560.04 v1(2652.56,560.04)
  Bottom Layer w11.81: C182.2@2625.98,560.04 v1@2651.57,560.04 ; SB18.2@2653.54,605.31 2653.54,561.02 v1(2652.56,560.04) R161.1@2694.88,560.04
STUSB1600_IRQOUTN: U12.9 U13.C4 | length 823.6
  Top Layer w3.94: v1(2870.07,1484.25) 2929.14,1484.25 U12.9@2935.04,1478.35
  Signal Layer 2 w3.94: v1(2165.35,1496.06) 2480.12,1496.06 2514.57,1461.61 2725.39,1461.61 2732.28,1468.5 2779.53,1468.5 2795.27,1484.25 v1(2870.07,1484.25)
  Bottom Layer w3.94: U13.C4@2145.67,1515.75 v1(2165.35,1496.06)
SW_IN: R9.2 U13.H8 U13.H9 | length 619.4
  Top Layer w15.75: R9.2@1830.71,2187.01 1879.92,2187.01 v3(1887.8,2179.13)
  Signal Layer 3 w15.75: v3(1887.8,2179.13) 1909.45,2157.48 1909.45,1769.69 1929.13,1750 v1(1929.13,1732.28) v1(1929.13,1692.91)
  Bottom Layer w19.68: v1(1929.13,1692.91) U13.H8@1948.82,1673.23 ; v1(1929.13,1732.28) U13.H9@1948.82,1712.6
SW_OUT: U13.G9 U13.G10 | length 95
  Signal Layer 3 w15.75: v1(1968.5,1732.28) v1(1968.5,1771.65)
  Bottom Layer w19.68: v1(1968.5,1732.28) U13.G9@1988.19,1712.6 ; v1(1968.5,1771.65) U13.G10@1988.19,1751.97
T_JTCK: SB20.1 U19.15 U19.26 | length 366.3
  Top Layer w3.94: U19.15@2706.69,402.56 v1(2706.69,471.46) 2716.54,481.3 U19.26@2942.91,481.3
  Bottom Layer w3.94: SB20.1@2649.61,471.46 v1(2706.69,471.46)
T_JTMS: R88.1 SB17.1 U19.27 | length 500.2
  Top Layer w3.94: v1(2690.94,664.37) 2691.93,663.39 2691.93,527.56 2718.5,500.98 U19.27@2942.91,500.98 2983.27,500.98 2994.09,511.81 R88.1@2998.03,511.81
  Bottom Layer w3.94: SB17.1@2649.61,664.37 v1(2690.94,664.37)
T_NRST: SB22.1 U19.18 | length 194.8
  Top Layer w3.94: v1(2649.61,359.25) 2758.86,359.25 2765.75,366.14 U19.18@2765.75,402.56
  Bottom Layer w3.94: v1(2649.61,359.25) SB22.1@2649.61,398.62
T_SWDIO_IN: R88.2 U19.25 | length 61.2
  Top Layer w3.94: U19.25@2942.91,461.61 2978.35,461.61 2993.11,476.38 R88.2@2998.03,476.38
T_SWO: SB19.1 U19.31 | length 126.8
  Top Layer w3.94: v1(2895.67,531.5) 2895.67,562.01 2913.39,579.72 U19.31@2942.91,579.72
  Bottom Layer w3.94: SB19.1@2854.33,532.48 2855.31,531.5 v1(2895.67,531.5)
TX0_N: U14.61 U32.9 | length 946
  Top Layer w3.94: U14.61@3010.83,1022.64 3026.57,1022.64 3031.89,1027.95 3125.58,1027.95 3345.47,808.06 3345.47,593.5 3427.17,511.81 3427.17,448.81 3458.85,417.13 3498.62,417.13 v1@3500,415.75
  Bottom Layer w3.94: v1(3500,411.42) 3500,415.75 3500.98,416.73 3515.35,416.73 3520.67,411.42 U32.9@3531.5,411.42
TX0_P: U14.62 U32.10 | length 947.5
  Top Layer w3.94: U14.62@3010.83,1042.32 3026.57,1042.32 3031.89,1037.01 3129.33,1037.01 3354.53,811.81 3354.53,597.25 3436.22,515.56 3436.22,452.56 3462.6,426.18 3495.08,426.18 v1(3500,431.1)
  Bottom Layer w3.94: v1(3500,431.1) 3500,426.77 3500.98,425.79 3515.35,425.79 3520.67,431.1 U32.10@3531.5,431.1
TX0C_N: CN9.9 U32.2 | length 120.3
  Top Layer w3.94: v1(3608.27,413.39) 3613.58,418.7 3633.46,418.7 3648.62,403.54 CN9.9@3681.1,403.54
  Bottom Layer w3.94: U32.2@3572.83,411.42 3582.68,411.42 3587.99,416.73 3604.92,416.73 v1(3608.27,413.39)
TX0C_P: CN9.7 U32.1 | length 122
  Top Layer w3.94: v1(3608.27,433.07) 3613.58,427.76 3633.46,427.76 3648.62,442.91 CN9.7@3681.1,442.91
  Bottom Layer w3.94: U32.1@3572.83,431.1 3582.68,431.1 3587.99,425.79 3600.98,425.79 v1(3608.27,433.07)
TX1_N: U14.64 U31.6 | length 929.8
  Top Layer w3.94: U14.64@3010.83,1081.69 3026.57,1081.69 3031.89,1087.01 3109.84,1087.01 3373.03,823.82 3373.03,607.28 3454.72,525.59 3454.72,493.1 3468.69,479.13 3494.29,479.13 v1(3500,473.43)
  Bottom Layer w3.94: v1(3500,473.43) 3500,477.76 3500.98,478.74 3515.35,478.74 3520.67,473.43 U31.6@3531.5,473.43
TX1_P: U14.65 U31.7 | length 929.5
  Top Layer w3.94: U14.65@3010.83,1101.38 3026.57,1101.38 3031.89,1096.06 3113.59,1096.06 3382.09,827.57 3382.09,611.03 3463.78,529.34 3463.78,496.85 3472.44,488.19 3495.08,488.19 v1(3500,493.11)
  Bottom Layer w3.94: v1(3500,493.11) 3500,488.78 3500.98,487.8 3515.35,487.8 3520.67,493.11 U31.7@3531.5,493.11
TX1C_N: CN9.6 U31.5 | length 121.6
  Top Layer w3.94: v1(3608.27,472.44) 3613.58,477.76 3633.46,477.76 3648.62,462.6 CN9.6@3681.1,462.6
  Bottom Layer w3.94: U31.5@3572.83,473.43 3583.66,473.43 3588.98,478.74 3601.97,478.74 v1(3608.27,472.44)
TX1C_P: CN9.4 U31.4 | length 120.7
  Top Layer w3.94: v1(3608.27,492.13) 3613.58,486.81 3633.46,486.81 3648.62,501.97 CN9.4@3681.1,501.97
  Bottom Layer w3.94: U31.4@3572.83,493.11 3583.66,493.11 3588.98,487.8 3603.94,487.8 v1(3608.27,492.13)
TX2_N: U14.67 U31.9 | length 914.3
  Top Layer w3.94: U14.67@3010.83,1140.75 3032.48,1140.75 3037.8,1146.06 3098.03,1146.06 3399.61,844.49 3399.61,622.04 3484.24,537.4 3495.08,537.4 v1(3500,532.48)
  Bottom Layer w3.94: v1(3500,532.48) 3500,536.81 3500.98,537.8 3515.35,537.8 3520.67,532.48 U31.9@3531.5,532.48
TX2_P: U14.68 U31.10 | length 914.6
  Top Layer w3.94: U14.68@3010.83,1160.43 3032.48,1160.43 3037.8,1155.12 3101.78,1155.12 3408.66,848.24 3408.66,625.79 3487.99,546.46 3494.29,546.46 v1(3500,552.17)
  Bottom Layer w3.94: v1(3500,552.17) 3500,547.83 3500.98,546.85 3515.35,546.85 3520.67,552.17 U31.10@3531.5,552.17
TX2C_N: CN9.3 U31.2 | length 121.6
  Top Layer w3.94: v1(3608.27,531.5) 3613.58,536.81 3633.46,536.81 3648.62,521.65 CN9.3@3681.1,521.65
  Bottom Layer w3.94: U31.2@3572.83,532.48 3582.68,532.48 3587.99,537.8 3601.97,537.8 v1(3608.27,531.5)
TX2C_P: CN9.1 U31.1 | length 120.7
  Top Layer w3.94: v1(3608.27,551.18) 3613.58,545.87 3633.46,545.87 3648.62,561.02 CN9.1@3681.1,561.02
  Bottom Layer w3.94: U31.1@3572.83,552.17 3582.68,552.17 3587.99,546.85 3603.94,546.85 v1(3608.27,551.18)
TXC_N: U14.58 U32.6 | length 966.8
  Top Layer w3.94: U14.58@3010.83,963.58 3027.56,963.58 3032.87,968.9 3143.31,968.9 3319.88,792.32 3319.88,578.74 3396.65,501.97 3396.65,405.51 3445.08,357.09 3495.28,357.09 v1(3500,352.36)
  Bottom Layer w3.94: v1(3500,352.36) 3500,356.69 3500.98,357.68 3515.35,357.68 3520.67,352.36 U32.6@3531.5,352.36
TXC_P: U14.59 U32.7 | length 967.3
  Top Layer w3.94: U14.59@3010.83,983.27 3027.56,983.27 3032.87,977.95 3147.06,977.95 3328.94,796.07 3328.94,582.49 3405.71,505.72 3405.71,409.26 3448.83,366.14 3494.09,366.14 v1(3500,372.05)
  Bottom Layer w3.94: v1(3500,372.05) 3500,367.72 3500.98,366.73 3515.35,366.73 3520.67,372.05 U32.7@3531.5,372.05
TXCC_N: CN9.12 U32.5 | length 120.3
  Top Layer w3.94: v1(3608.27,354.33) 3613.58,359.65 3633.46,359.65 3648.62,344.49 CN9.12@3681.1,344.49
  Bottom Layer w3.94: U32.5@3572.83,352.36 3583.66,352.36 3588.98,357.68 3604.92,357.68 v1(3608.27,354.33)
TXCC_P: CN9.10 U32.4 | length 122
  Top Layer w3.94: v1(3608.27,374.02) 3613.58,368.7 3633.46,368.7 3648.62,383.86 CN9.10@3681.1,383.86
  Bottom Layer w3.94: U32.4@3572.83,372.05 3583.66,372.05 3588.98,366.73 3600.98,366.73 v1(3608.27,374.02)
UART4_RX: R77.2 U13.M18 | length 2333
  Top Layer w3.94: v1(2485.43,799.8) 2485.43,800.39 R77.2@2521.65,836.61
  Signal Layer 2 w3.94: v1(1797.24,2139.76) 1806.59,2149.11 2054.82,2149.11 2084.84,2179.13 2127.75,2179.13 2131.69,2175.2 v1(2496.06,2175.2)
  Signal Layer 3 w3.94: v1(2485.43,799.8) 2414.96,870.28 2414.96,1065.8 2483.07,1133.91 2483.07,1329.53 2519.68,1366.14 2519.68,1462.4 2482.62,1499.46 2482.62,1860.58 2515.75,1893.7 2515.75,2112.65 2500,2128.4 2500,2175.2 2498.03,2173.23 v1(2496.06,2175.2)
  Bottom Layer w3.94: U13.M18@1791.34,2066.93 1791.34,2133.86 v1(1797.24,2139.76)
UART4_TX: R72.1 U13.C14 | length 2023.5
  Top Layer w3.94: R72.1@2773.62,792.91 2817.32,792.91 v1(2818.9,791.34)
  Signal Layer 2 w3.94: v1(2165.35,1929.13) 2350.39,1929.13 2360.24,1938.98 2402.02,1938.98 2411.87,1929.13 2677.17,1929.13 2692.91,1913.39 2783.46,1913.39 2846.46,1850.39 v1(2846.46,1846.46)
  Signal Layer 3 w3.94: v1(2818.9,791.34) 2889.57,791.34 2951.77,853.54 2951.77,967.07 2980.31,995.61 2980.31,1177.17 2877.95,1279.53 2877.95,1433.07 2840.55,1470.47 2840.55,1731.55 2842.52,1733.52 2842.52,1842.04 2842.28,1842.28 v1(2846.46,1846.46)
  Bottom Layer w3.94: U13.C14@2145.67,1909.45 v1(2165.35,1929.13)
USART2_CTS: U8.5 U13.T11 | length 2022.3
  Top Layer w3.94: v1(63.95,1864.17) U8.5@99.41,1864.17 ; v1(334.65,1574.8) 383.86,1574.8 448.82,1639.76 775.11,1639.76 779.05,1635.83 1192.91,1635.83 1253.94,1574.8 1418.62,1574.8 1482.28,1638.47 1482.28,1757.68 1535.63,1811.02 v1(1614.17,1811.02)
  Bottom Layer w3.94: v1(63.95,1864.17) 156.94,1864.17 167.32,1853.8 167.32,1835.22 260.84,1741.71 260.84,1679.43 295.28,1644.99 295.28,1610.78 331.25,1574.8 v1(334.65,1574.8) ; v1(1614.17,1811.02) U13.T11@1633.86,1791.34
USART2_RTS: U8.4 U13.V10 | length 1764.8
  Top Layer w3.94: v1(75.8,1881.89) U8.4@99.41,1881.89
  Signal Layer 2 w3.94: v1(75.8,1881.89) 89.58,1868.11 89.58,1775.14 216.1,1648.62 233.27,1648.62 297.24,1584.65 311.21,1584.65 317.12,1590.55 350.39,1590.55 391.73,1631.89 1401.57,1631.89 1496.06,1726.38 v1(1496.06,1751.97)
  Bottom Layer w3.94: v1(1496.06,1751.97) U13.V10@1555.12,1751.97
USART2_RX: TP27.1 U8.3 U13.T10 | length 2107
  Top Layer w3.94: v1(63.95,1899.61) U8.3@99.41,1899.61
  Signal Layer 2 w3.94: v1(1452.76,1492.13) 1513.78,1553.15 1524.72,1553.15 1537.4,1565.83 1537.4,1576.77 1614.17,1653.54 v1(1614.17,1771.65)
  Bottom Layer w3.94: v1(63.95,1899.61) 143.78,1899.61 183.07,1860.32 183.07,1841.74 276.58,1748.23 276.58,1690.98 286.96,1680.6 297.75,1680.6 558.46,1419.88 711.22,1419.88 TP27.1@732.28,1440.94 753.35,1419.88 1020.28,1419.88 1028.74,1411.42 1379.92,1411.42 1452.76,1484.25 v1(1452.76,1492.13) ; v1(1614.17,1771.65) U13.T10@1633.86,1751.97
USART2_TX: TP28.1 U8.2 U13.U10 | length 2087.2
  Top Layer w3.94: v1(75.8,1917.32) U8.2@99.41,1917.32
  Signal Layer 2 w3.94: v1(1425.2,1488.19) 1498.04,1561.02 1521.46,1561.02 1529.53,1569.1 1529.53,1765.75 v1(1535.43,1771.65)
  Bottom Layer w3.94: v1(75.8,1917.32) 137.2,1917.32 187.67,1866.86 221.01,1866.86 319.89,1767.97 319.89,1677.04 555.99,1440.94 TP28.1@678.15,1440.94 695.87,1458.66 1065.26,1458.66 1066.94,1460.35 1182.65,1460.35 1223.7,1419.29 1356.31,1419.29 v1(1425.2,1488.19) ; v1(1535.43,1771.65) 1541.34,1765.75 1561.02,1765.75 1574.8,1751.97 U13.U10@1594.49,1751.97
USB1_N: U7.30 U13.K18 | length 1187.5
  Top Layer w3.94: v1(1870.08,2125.98) 1889.57,2125.98 1901.77,2113.78 1908.61,2113.78 1945.82,2076.57 2276.52,2076.57 2324.8,2028.3 2324.8,1836.61 2362.2,1799.21 2362.2,1736.22 2375.98,1722.44 2496.26,1722.44 2500.2,1718.5 2545.52,1718.5 2604.33,1777.31 2604.33,1797.24 2598.43,1803.15 U7.30@2598.43,1826.77
  Bottom Layer w3.94: U13.K18@1870.08,2066.93 v1(1870.08,2125.98)
USB1_P: U7.31 U13.K17 | length 1203.2
  Top Layer w3.94: v1(1889.76,2106.3) 1905.51,2106.3 1942.72,2069.09 2273.43,2069.09 2317.32,2025.2 2317.32,1833.52 2318.9,1831.94 2318.9,1830.71 2354.33,1795.28 2354.33,1736.22 2354.72,1735.83 2354.72,1733.12 2372.89,1714.96 2493.16,1714.96 2497.1,1711.02 2548.62,1711.02 2561.61,1724.02 2611.81,1774.21 2611.81,1799.21 2618.11,1805.51 U7.31@2618.11,1826.77
  Bottom Layer w3.94: U13.K17@1870.08,2027.56 1870.08,2047.24 1889.76,2066.93 v1(1889.76,2106.3)
USB1CN25_N: CN5.T2 U9.5 | length 449.7
  Top Layer w3.94: U9.5@3135.83,1935.04 3149.61,1935.04 3155.71,1941.14 3236.02,1941.14 3378.35,1798.82 3378.35,1741 3390.8,1728.54 3415.35,1728.54 3439.76,1704.13 CN5.T2@3439.76,1692.91
USB1CN25_P: CN5.T3 U9.6 | length 449.7
  Top Layer w3.94: U9.6@3135.83,1954.72 3149.61,1954.72 3155.71,1948.62 3239.12,1948.62 3385.83,1801.92 3385.83,1744.09 3393.9,1736.02 3415.35,1736.02 3439.76,1760.43 CN5.T3@3439.76,1771.65
USB2_N: U13.J17 U29.2 | length 2246.1
  Top Layer w3.94: v1(1929.13,2007.87) 1935.43,2014.17 1935.43,2014.91 1961.96,2041.44 2202.66,2041.44 2239.76,2004.33 2239.76,1883.86 2238.39,1883.86 2230.32,1875.79 2230.32,1860.24 2277.95,1812.6 2292.27,1812.6 2304.72,1800.14 2304.72,1755.07 2360.24,1699.56 2360.24,1580.71 2340.55,1561.02 2340.55,1486.22 2381.32,1445.45 2381.32,1435.14 2389.4,1427.06 2399.71,1427.06 2448.82,1377.95 2477.56,1377.95 v1(2485.24,1385.63)
  Bottom Layer w3.94: U13.J17@1909.45,2027.56 v1(1929.13,2007.87) ; v1(2485.24,1385.63) 2492.89,1377.98 2524.88,1377.98 2557.53,1410.63 2855.85,1410.63 2930.26,1336.22 3083.07,1336.22 3322.05,1097.24 3408.27,1097.24 3414.37,1103.35 U29.2@3422.24,1103.35
USB2_P: U13.J18 U29.1 | length 2335
  Top Layer w3.94: v1(1889.76,2007.87) 1909.45,2007.87 1921.65,1995.67 1921.85,1995.67 1923.43,1994.09 1934.84,1994.09 1942.91,2002.17 1942.91,2011.81 1965.06,2033.96 2199.56,2033.96 2232.28,2001.23 2232.28,1888.33 2222.83,1878.88 2222.83,1857.14 2274.85,1805.12 2289.17,1805.12 2297.24,1797.05 2297.24,1751.97 2352.76,1696.46 2352.76,1583.81 2333.07,1564.12 2333.07,1483.12 2373.84,1442.35 2373.84,1432.04 2386.3,1419.58 2396.61,1419.58 2445.72,1370.47 2480.71,1370.47 v1(2485.24,1365.95)
  Bottom Layer w3.94: v1(1889.76,2007.87) 1889.76,2047.24 U13.J18@1909.45,2066.93 ; v1(2485.24,1365.95) 2489.79,1370.5 2527.98,1370.5 2560.63,1403.15 2852.76,1403.15 2927.17,1328.74 3079.72,1328.74 3318.7,1089.76 3408.27,1089.76 3414.37,1083.66 U29.1@3422.24,1083.66
USB2CN25_N: CN5.B2 U6.5 | length 598.2
  Top Layer w3.94: U6.5@3135.83,2029.53 3143.7,2029.53 3149.8,2035.63 3186.81,2035.63 3402.17,1820.28 3481.89,1820.28 3492.13,1810.04 3492.13,1739.17 3502.56,1728.74 3515.75,1728.74 3542.91,1701.57 CN5.B2@3542.91,1692.91
USB2CN25_P: CN5.B3 U6.6 | length 597.8
  Top Layer w3.94: U6.6@3135.83,2049.21 3143.7,2049.21 3149.8,2043.11 3189.91,2043.11 3405.26,1827.76 3484.99,1827.76 3490.53,1822.22 3499.61,1813.14 3499.61,1742.27 3505.66,1736.22 3515.75,1736.22 3542.91,1763.39 CN5.B3@3542.91,1771.65
USB3CN26_N: CN1.T2 U2.5 | length 474.1
  Top Layer w3.94: U2.5@3135.83,2368.11 3143.7,2368.11 3149.02,2373.43 3234.4,2373.43 3251.4,2390.43 3251.4,2487.62 3261.81,2498.03 3355.31,2498.03 3374.02,2479.33 3374.02,2446.11 3382.93,2437.2 3404.13,2437.2 CN1.T2@3439.76,2401.57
